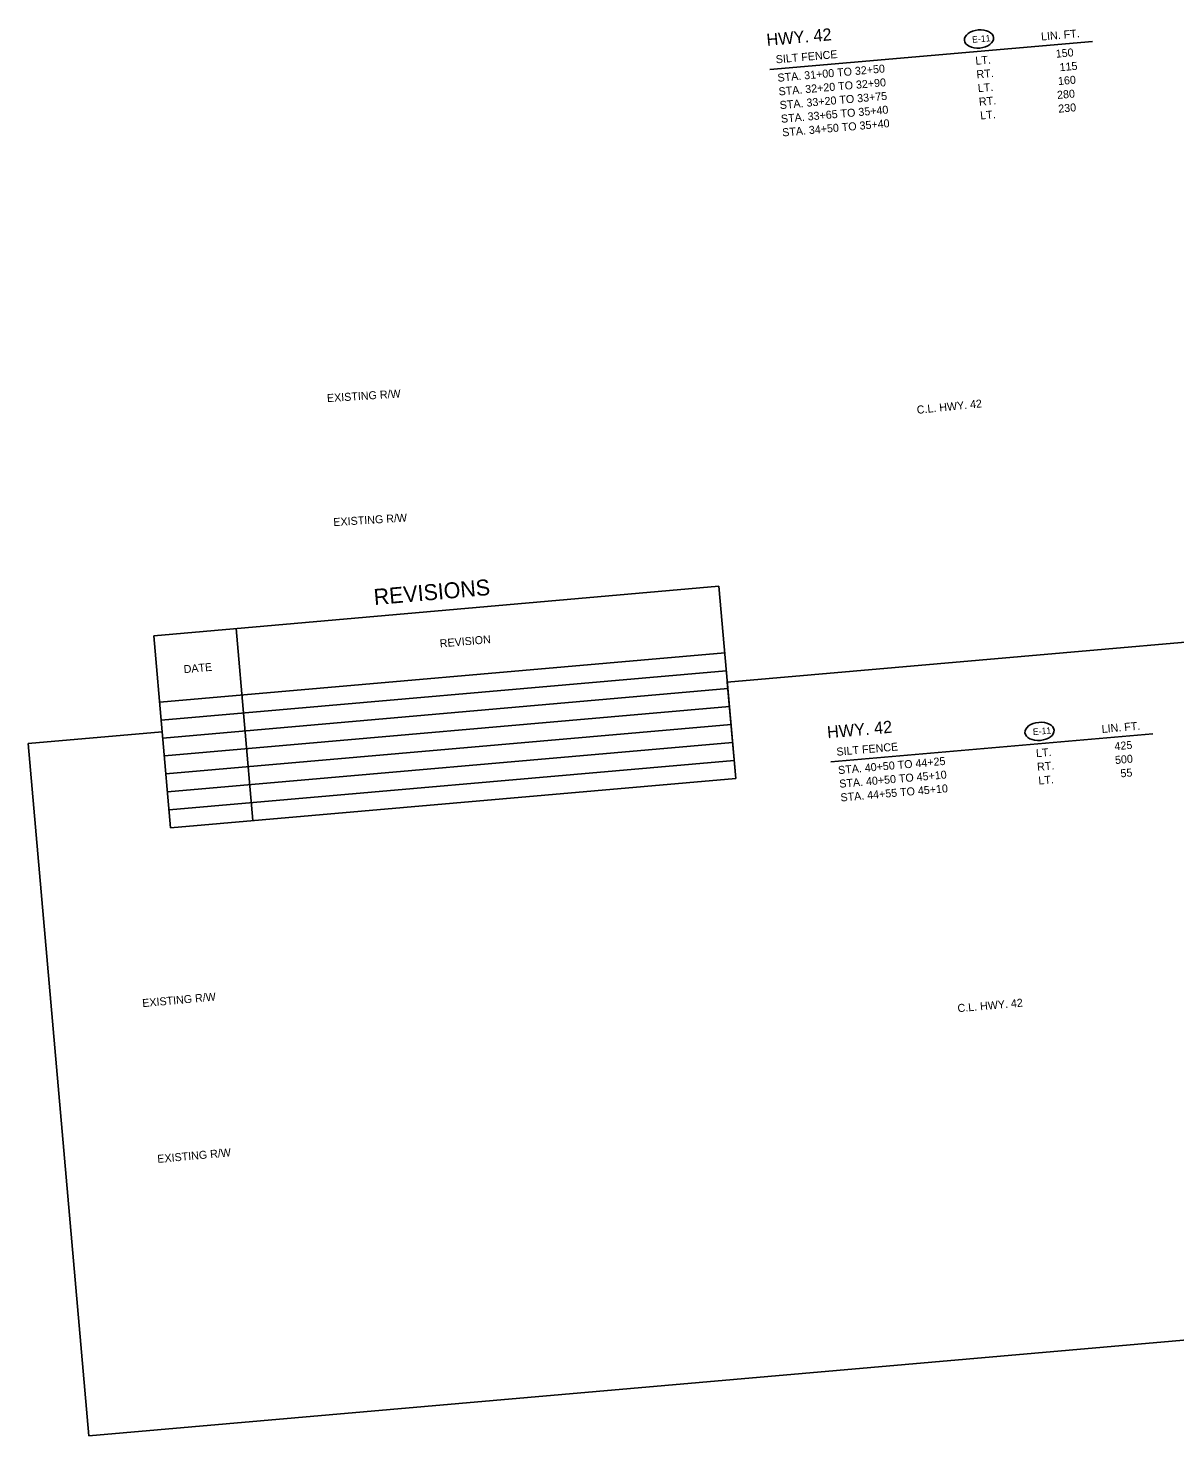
# Model space of a CAD drawing. Extents: x 1734805 to 1736440, y 377441 to 378578.
# Drawn here: x 1734805 to 1735664, y 377441 to 378497 of the extents above; entities that cross this region are included whole.
import ezdxf

# ---------------------------------------------------------------- set-up
doc = ezdxf.new("R2010")
doc.units = 0
for name, color, linetype in [('44', 7, 'Continuous'), ('G-Border-Sheet', 7, 'Continuous'), ('Level 1', 7, 'Continuous'), ('Level 44', 7, 'Continuous'), ('R_Draft', 7, 'Continuous')]:
    doc.layers.add(name, color=color, linetype=linetype)

msp = doc.modelspace()

# ---------------------------------------------------------------- linework, layer by layer
at = {"layer": '44'}
for p, q in [((1735361.1, 378466), (1735602.7, 378487.1)), ((1735406.6, 377946.8), (1735648.1, 377967.9))]:
    msp.add_line(p, q, dxfattribs=at)
at = {"layer": 'G-Border-Sheet'}
for p, q in [((1734850.6, 377441.5), (1734805.2, 377960.6)), ((1736439.9, 377580.5), (1734850.6, 377441.5))]:
    msp.add_line(p, q, dxfattribs=at)
msp.add_lwpolyline([(1734805.2, 377960.6), (1734905.7, 377969.4), (1734905.7, 377969.4), (1734912, 377897.5), (1735335.4, 377934.5), (1735329.1, 378006.5), (1735952.7, 378061), (1735947.4, 378121.3), (1736288.7, 378151.2), (1736294, 378090.9), (1736394.5, 378099.7)], dxfattribs=at)
at = {"layer": 'Level 1'}
for centre in [(1735517.7, 378488.9), (1735563.1, 377969.7)]:
    msp.add_ellipse(centre, major_axis=(10.9, 1), ratio=0.622952, dxfattribs=at)
at = {"layer": 'R_Draft'}
for p, q in [((1734899.4, 378041.4), (1735322.8, 378078.5)), ((1735322.8, 378078.5), (1735335.4, 377934.5)), ((1734961, 378046.8), (1734973.6, 377902.9)), ((1734899.4, 378041.4), (1734912, 377897.5)), ((1734903.8, 377991.6), (1735327.2, 378028.6)), ((1734905, 377978.2), (1735328.3, 378015.2)), ((1734906.1, 377964.7), (1735329.5, 378001.8)), ((1734907.3, 377951.3), (1735330.7, 377988.3)), ((1734907.3, 377951.3), (1735330.7, 377988.3)), ((1734908.5, 377937.8), (1735331.9, 377974.9)), ((1734909.7, 377924.4), (1735333, 377961.4)), ((1734910.8, 377910.9), (1735334.2, 377948)), ((1734912, 377897.5), (1735335.4, 377934.5))]:
    msp.add_line(p, q, dxfattribs=at)

# ---------------------------------------------------------------- texts
at = {"layer": '44'}
for s, p in [('LIN. FT.', (1735564.5, 378487.7)), ('SILT FENCE      ', (1735365.7, 378470.6)), ('150', (1735575.5, 378474.8)), ('STA. 31+00 TO 32+50', (1735367, 378456.8)), ('LT.', (1735515.3, 378469.5)), ('RT.', (1735516.1, 378459.3)), ('115', (1735578.4, 378464.7)), ('STA. 32+20 TO 32+90', (1735367.8, 378446.5)), ('LT.', (1735517.1, 378449)), ('160', (1735577.2, 378454.3)), ('STA. 33+20 TO 33+75', (1735368.7, 378436.3)), ('RT.', (1735517.9, 378438.8)), ('280', (1735576.5, 378443.9)), ('STA. 33+65 TO 35+40', (1735369.6, 378426)), ('LT.', (1735518.9, 378428.5)), ('230', (1735577.4, 378433.6)), ('STA. 34+50 TO 35+40', (1735370.5, 378415.8)), ('LIN. FT.', (1735609.9, 377968.5)), ('SILT FENCE      ', (1735411.2, 377951.4)), ('425', (1735619.5, 377955.5)), ('STA. 40+50 TO 44+25', (1735412.4, 377937.6)), ('LT.', (1735560.7, 377950.3)), ('500', (1735619.9, 377945.2)), ('STA. 40+50 TO 45+10', (1735413.3, 377927.4)), ('RT.', (1735561.5, 377940.1)), ('55', (1735624, 377935.2)), ('STA. 44+55 TO 45+10', (1735414.2, 377917.1)), ('LT.', (1735562.5, 377929.8))]:
    msp.add_text(s, height=6, rotation=5, dxfattribs=at).set_placement(p)
at = {"layer": 'Level 1'}
for p in [(1735512.8, 378486), (1735558.3, 377966.9)]:
    msp.add_text('E-11', height=4.88, rotation=5, dxfattribs=at).set_placement(p)
at = {"layer": 'Level 44'}
for p in [(1735358.9, 378483.7), (1735404.3, 377964.5)]:
    msp.add_text('HWY. 42', height=9.14, rotation=5, dxfattribs=at).set_placement(p)
at = {"layer": 'R_Draft'}
for s, height, rotation, p in [('EXISTING R/W', 6, 3.6186, (1735029.3, 378216.6)), ('C.L. HWY. 42', 6, 5.7558, (1735471.4, 378207.8)), ('EXISTING R/W', 6, 3.6186, (1735034.1, 378123.6)), ('REVISIONS', 12, 5, (1735064.7, 378064.4)), ('REVISION', 6, 5, (1735113.9, 378032.6)), ('DATE', 6, 5, (1734922, 378013.3)), ('EXISTING R/W', 6, 5.2121, (1734891, 377762.9)), ('C.L. HWY. 42', 6, 5.0261, (1735501.9, 377759.1)), ('EXISTING R/W', 6, 5.2121, (1734902.3, 377646.1))]:
    msp.add_text(s, height=height, rotation=rotation, dxfattribs=at).set_placement(p)

doc.saveas('drawing.dxf')
